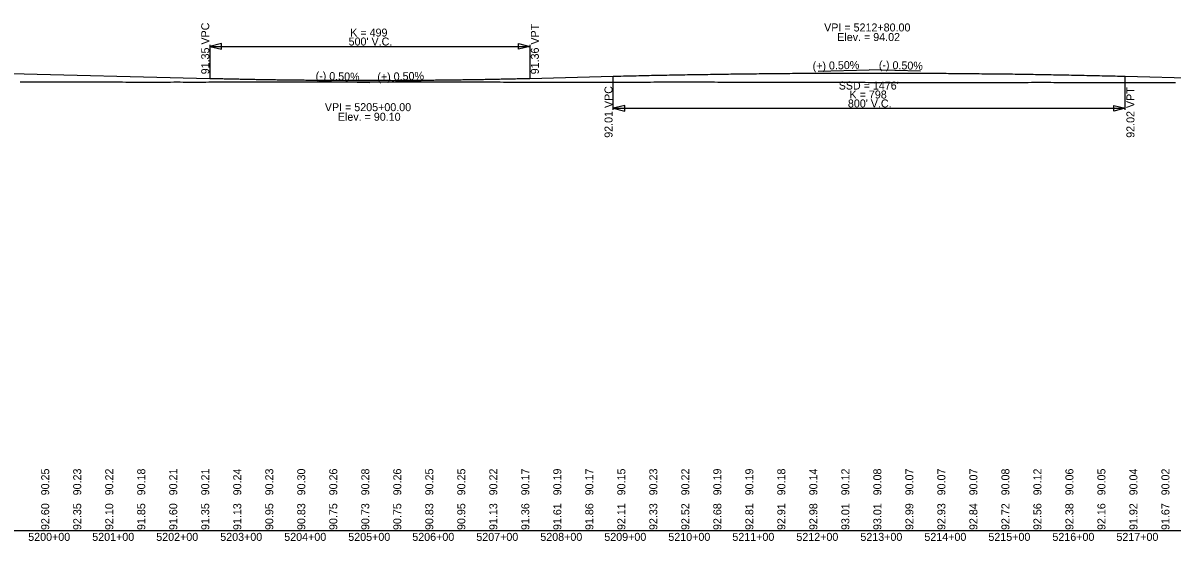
# Model space of a CAD drawing. Extents: x 2147288 to 2220488, y 740833 to 759333.
# Drawn here: x 2152339 to 2154136, y 742067 to 742877 of the extents above; entities that cross this region are included whole.
import ezdxf

# ---------------------------------------------------------------- set-up
doc = ezdxf.new("R2010")
doc.units = 0
for name, color, linetype in [('RD_DDB_GradeTX', 7, 'Continuous'), ('RD_DDB_Profile_EX', 7, 'Continuous'), ('RD_DDB_Profile_Lbl', 7, 'Continuous'), ('RD_DDB_Profile_PR', 7, 'Continuous'), ('RD_DDB_StaTX', 7, 'Continuous'), ('RD_DDB_StripGrade', 7, 'Continuous'), ('RD_DDB_VCLbl', 7, 'Continuous'), ('RD_GPK_Profile_Cell', 7, 'Continuous')]:
    doc.layers.add(name, color=color, linetype=linetype)

msp = doc.modelspace()

# ---------------------------------------------------------------- linework, layer by layer
at = {"layer": 'RD_DDB_GradeTX'}
for p, q in [((2153581.1, 742801.5), (2153661.1, 742803.5)), ((2153741.1, 742801.5), (2153661.1, 742803.5)), ((2152801.1, 742785.9), (2152881.1, 742783.9)), ((2152961.1, 742785.9), (2152881.1, 742783.9))]:
    msp.add_line(p, q, dxfattribs=at)
at = {"layer": 'RD_DDB_Profile_EX'}
for points in [[(2152334.6, 742784.9), (2152339.6, 742784.9), (2152344.6, 742784.8), (2152349.6, 742784.8), (2152354.6, 742784.8), (2152359.6, 742784.8), (2152364.6, 742784.7), (2152369.6, 742784.7), (2152374.6, 742784.7), (2152379.6, 742784.7), (2152384.6, 742784.7), (2152389.6, 742784.6), (2152394.6, 742784.6), (2152399.6, 742784.6), (2152404.6, 742784.6), (2152409.6, 742784.6), (2152414.6, 742784.6), (2152419.6, 742784.6), (2152424.6, 742784.6), (2152429.6, 742784.6), (2152434.6, 742784.6), (2152439.6, 742784.6), (2152444.6, 742784.6), (2152449.6, 742784.6), (2152454.6, 742784.6), (2152459.6, 742784.6), (2152464.6, 742784.6), (2152469.6, 742784.6), (2152474.6, 742784.5), (2152479.6, 742784.5), (2152484.6, 742784.5), (2152489.6, 742784.5), (2152494.6, 742784.5), (2152499.6, 742784.4), (2152504.6, 742784.4), (2152509.6, 742784.4), (2152514.6, 742784.4), (2152519.6, 742784.4), (2152524.6, 742784.4), (2152529.6, 742784.3), (2152534.6, 742784.3)], [(2152534.6, 742784.3), (2152539.6, 742784.3), (2152544.6, 742784.3), (2152549.6, 742784.3), (2152554.6, 742784.4), (2152559.6, 742784.4), (2152564.6, 742784.4), (2152569.6, 742784.4), (2152574.6, 742784.5), (2152579.6, 742784.5), (2152584.6, 742784.5), (2152589.6, 742784.4), (2152594.6, 742784.4), (2152599.6, 742784.4), (2152604.6, 742784.4), (2152609.6, 742784.4), (2152614.6, 742784.4), (2152619.6, 742784.4), (2152624.6, 742784.4), (2152629.6, 742784.5), (2152634.6, 742784.5), (2152639.6, 742784.5), (2152644.6, 742784.5), (2152649.6, 742784.6), (2152654.6, 742784.6), (2152659.6, 742784.6), (2152664.6, 742784.6), (2152669.6, 742784.6), (2152674.6, 742784.6), (2152679.6, 742784.6), (2152684.6, 742784.6), (2152689.6, 742784.7), (2152694.6, 742784.7), (2152699.6, 742784.7), (2152704.6, 742784.6), (2152709.6, 742784.6), (2152714.6, 742784.6), (2152719.6, 742784.6), (2152724.6, 742784.6), (2152729.6, 742784.6), (2152734.6, 742784.6), (2152739.6, 742784.6), (2152744.6, 742784.6), (2152749.6, 742784.6), (2152754.6, 742784.7), (2152759.6, 742784.7), (2152764.6, 742784.8), (2152769.6, 742784.8), (2152774.6, 742784.9), (2152779.6, 742784.9), (2152784.6, 742784.9), (2152789.6, 742784.9), (2152794.6, 742784.8), (2152799.6, 742784.8), (2152804.6, 742784.8), (2152809.6, 742784.8), (2152814.6, 742784.8), (2152819.6, 742784.8), (2152824.6, 742784.8), (2152829.6, 742784.7), (2152834.6, 742784.7), (2152839.6, 742784.7), (2152844.6, 742784.7), (2152849.6, 742784.7), (2152854.6, 742784.7), (2152859.6, 742784.7), (2152864.6, 742784.8), (2152869.6, 742784.8), (2152874.6, 742784.8), (2152879.6, 742784.8), (2152884.6, 742784.8), (2152889.6, 742784.9), (2152894.6, 742784.9), (2152899.6, 742784.8), (2152904.6, 742784.8), (2152909.6, 742784.8), (2152914.6, 742784.8), (2152919.6, 742784.8), (2152924.6, 742784.8), (2152929.6, 742784.7), (2152934.6, 742784.7), (2152939.6, 742784.7), (2152944.6, 742784.7), (2152949.6, 742784.7), (2152954.6, 742784.7), (2152959.6, 742784.7), (2152964.6, 742784.7), (2152969.6, 742784.7), (2152974.6, 742784.7), (2152979.6, 742784.7), (2152984.6, 742784.7), (2152989.6, 742784.7), (2152994.6, 742784.7), (2152999.6, 742784.7), (2153004.6, 742784.8), (2153009.6, 742784.8), (2153014.6, 742784.8), (2153019.6, 742784.7), (2153024.6, 742784.7), (2153029.6, 742784.7), (2153034.6, 742784.7)], [(2153034.6, 742784.7), (2153039.6, 742784.7), (2153044.6, 742784.8), (2153049.6, 742784.8), (2153054.6, 742784.9), (2153059.6, 742784.9), (2153064.6, 742784.8), (2153069.6, 742784.7), (2153074.6, 742784.6), (2153079.6, 742784.6), (2153084.6, 742784.5), (2153089.6, 742784.4), (2153094.6, 742784.4), (2153099.6, 742784.3), (2153104.6, 742784.3), (2153109.6, 742784.3), (2153114.6, 742784.3), (2153119.6, 742784.3), (2153124.6, 742784.3), (2153129.6, 742784.3), (2153134.6, 742784.3), (2153139.6, 742784.3), (2153144.6, 742784.3), (2153149.6, 742784.3), (2153154.6, 742784.3), (2153159.6, 742784.3), (2153164.6, 742784.3), (2153169.6, 742784.3), (2153174.6, 742784.4), (2153179.6, 742784.4), (2153184.6, 742784.4), (2153189.6, 742784.4), (2153194.6, 742784.3), (2153199.6, 742784.4), (2153204.6, 742784.4), (2153209.6, 742784.4), (2153214.6, 742784.4), (2153219.6, 742784.3), (2153224.6, 742784.3), (2153229.6, 742784.3), (2153234.6, 742784.3), (2153239.6, 742784.2), (2153244.6, 742784.2), (2153249.6, 742784.1), (2153254.6, 742784), (2153259.6, 742784.1), (2153264.6, 742784.1), (2153269.6, 742784.1), (2153274.6, 742784.1), (2153279.6, 742784.2), (2153284.6, 742784.2), (2153289.6, 742784.2), (2153294.6, 742784.3), (2153299.6, 742784.3), (2153304.6, 742784.4), (2153309.6, 742784.4), (2153314.6, 742784.3), (2153319.6, 742784.4), (2153324.6, 742784.5), (2153329.6, 742784.6), (2153334.6, 742784.6), (2153339.6, 742784.6), (2153344.6, 742784.6), (2153349.6, 742784.6), (2153354.6, 742784.6), (2153359.6, 742784.6), (2153364.6, 742784.6), (2153369.6, 742784.5), (2153374.6, 742784.5), (2153379.6, 742784.5), (2153384.6, 742784.6), (2153389.6, 742784.6), (2153394.6, 742784.6), (2153399.6, 742784.5), (2153404.6, 742784.5), (2153409.6, 742784.5), (2153414.6, 742784.5), (2153419.6, 742784.5), (2153424.6, 742784.4), (2153429.6, 742784.4), (2153434.6, 742784.3), (2153439.6, 742784.3), (2153444.6, 742784.3), (2153449.6, 742784.3), (2153454.6, 742784.3), (2153459.6, 742784.3), (2153464.6, 742784.3), (2153469.6, 742784.4), (2153474.6, 742784.4), (2153479.6, 742784.4), (2153484.6, 742784.4), (2153489.6, 742784.4), (2153494.6, 742784.4), (2153499.6, 742784.4), (2153504.6, 742784.4), (2153509.6, 742784.3), (2153514.6, 742784.3), (2153519.6, 742784.4), (2153524.6, 742784.4), (2153529.6, 742784.3), (2153534.6, 742784.3)], [(2153534.6, 742784.3), (2153539.6, 742784.3), (2153544.6, 742784.3), (2153549.6, 742784.3), (2153554.6, 742784.3), (2153559.6, 742784.2), (2153564.6, 742784.2), (2153569.6, 742784.2), (2153574.6, 742784.2), (2153579.6, 742784.2), (2153584.6, 742784.1), (2153589.6, 742784.1), (2153594.6, 742784.1), (2153599.6, 742784.1), (2153604.6, 742784), (2153609.6, 742784), (2153614.6, 742784), (2153619.6, 742784), (2153624.6, 742784), (2153629.6, 742784), (2153634.6, 742784), (2153639.6, 742784), (2153644.6, 742784), (2153649.6, 742784), (2153654.6, 742784), (2153659.6, 742783.9), (2153664.6, 742783.9), (2153669.6, 742783.9), (2153674.6, 742783.8), (2153679.6, 742783.8), (2153684.6, 742783.8), (2153689.6, 742783.8), (2153694.6, 742783.8), (2153699.6, 742783.8), (2153704.6, 742783.8), (2153709.6, 742783.8), (2153714.6, 742783.8), (2153719.6, 742783.8), (2153724.6, 742783.8), (2153729.6, 742783.8), (2153734.6, 742783.8), (2153739.6, 742783.8), (2153744.6, 742783.8), (2153749.6, 742783.8), (2153754.6, 742783.8), (2153759.6, 742783.8), (2153764.6, 742783.8), (2153769.6, 742783.8), (2153774.6, 742783.8), (2153779.6, 742783.8), (2153784.6, 742783.8), (2153789.6, 742783.8), (2153794.6, 742783.8), (2153799.6, 742783.8), (2153804.6, 742783.7), (2153809.6, 742783.7), (2153814.6, 742783.7), (2153819.6, 742783.7), (2153824.6, 742783.8), (2153829.6, 742783.8), (2153834.6, 742783.8), (2153839.6, 742783.8), (2153844.6, 742783.8), (2153849.6, 742783.8), (2153854.6, 742783.8), (2153859.6, 742783.8), (2153864.6, 742783.8), (2153869.6, 742783.8), (2153874.6, 742783.8), (2153879.6, 742783.8), (2153884.6, 742783.8), (2153889.6, 742783.9), (2153894.6, 742783.9), (2153899.6, 742783.9), (2153904.6, 742783.9), (2153909.6, 742783.9), (2153914.6, 742784), (2153919.6, 742784), (2153924.6, 742784), (2153929.6, 742784), (2153934.6, 742784), (2153939.6, 742784), (2153944.6, 742784), (2153949.6, 742783.9), (2153954.6, 742783.9), (2153959.6, 742783.8), (2153964.6, 742783.8), (2153969.6, 742783.8), (2153974.6, 742783.8), (2153979.6, 742783.7), (2153984.6, 742783.7), (2153989.6, 742783.7), (2153994.6, 742783.7), (2153999.6, 742783.7), (2154004.6, 742783.7), (2154009.6, 742783.7), (2154014.6, 742783.7), (2154019.6, 742783.7), (2154024.6, 742783.7), (2154029.6, 742783.7), (2154034.6, 742783.7)], [(2154034.6, 742783.7), (2154039.6, 742783.7), (2154044.6, 742783.7), (2154049.6, 742783.7), (2154054.6, 742783.7), (2154059.6, 742783.7), (2154064.6, 742783.7), (2154069.6, 742783.6), (2154074.6, 742783.6), (2154079.6, 742783.6), (2154084.6, 742783.6), (2154089.6, 742783.6), (2154094.6, 742783.6), (2154099.6, 742783.6), (2154104.6, 742783.6), (2154109.6, 742783.6), (2154114.6, 742783.5), (2154119.6, 742783.5), (2154124.6, 742783.6), (2154129.6, 742783.5), (2154134.6, 742783.5), (2154139.6, 742783.5)]]:
    msp.add_lwpolyline(points, dxfattribs=at)
at = {"layer": 'RD_DDB_Profile_PR'}
for p, q in [((2152281.1, 742798.9), (2152631.1, 742790.2)), ((2153131.1, 742790.2), (2153261.1, 742793.5)), ((2154061.1, 742793.5), (2154231.1, 742789.3))]:
    msp.add_line(p, q, dxfattribs=at)
for points in [[(2152631.1, 742790.2), (2152641.1, 742789.9), (2152651.1, 742789.7), (2152661.1, 742789.5), (2152671.1, 742789.3), (2152681.1, 742789.1), (2152691.1, 742788.9), (2152701.1, 742788.7), (2152711.1, 742788.5), (2152721.1, 742788.3), (2152731.1, 742788.2), (2152741.1, 742788), (2152751.1, 742787.9), (2152761.1, 742787.8), (2152771.1, 742787.7), (2152781.1, 742787.6), (2152791.1, 742787.5), (2152801.1, 742787.4), (2152811.1, 742787.3), (2152821.1, 742787.2), (2152831.1, 742787.2), (2152841.1, 742787.1), (2152851.1, 742787.1), (2152861.1, 742787.1), (2152871.1, 742787.1), (2152881.1, 742787.1), (2152891.1, 742787.1), (2152901.1, 742787.1), (2152911.1, 742787.1), (2152921.1, 742787.1), (2152931.1, 742787.2), (2152941.1, 742787.2), (2152951.1, 742787.3), (2152961.1, 742787.4), (2152971.1, 742787.5), (2152981.1, 742787.6), (2152991.1, 742787.7), (2153001.1, 742787.8), (2153011.1, 742787.9), (2153021.1, 742788.1), (2153031.1, 742788.2), (2153041.1, 742788.4), (2153051.1, 742788.5), (2153061.1, 742788.7), (2153071.1, 742788.9), (2153081.1, 742789.1), (2153091.1, 742789.3), (2153101.1, 742789.5), (2153111.1, 742789.7), (2153121.1, 742790), (2153131.1, 742790.2)], [(2153261.1, 742793.5), (2153277.1, 742793.9), (2153293.1, 742794.2), (2153309.1, 742794.6), (2153325.1, 742795), (2153341.1, 742795.3), (2153357.1, 742795.6), (2153373.1, 742795.9), (2153389.1, 742796.2), (2153405.1, 742796.4), (2153421.1, 742796.7), (2153437.1, 742796.9), (2153453.1, 742797.1), (2153469.1, 742797.3), (2153485.1, 742797.5), (2153501.1, 742797.7), (2153517.1, 742797.9), (2153533.1, 742798), (2153549.1, 742798.1), (2153565.1, 742798.2), (2153581.1, 742798.3), (2153597.1, 742798.4), (2153613.1, 742798.4), (2153629.1, 742798.5), (2153645.1, 742798.5), (2153661.1, 742798.5), (2153677.1, 742798.5), (2153693.1, 742798.5), (2153709.1, 742798.4), (2153725.1, 742798.4), (2153741.1, 742798.3), (2153757.1, 742798.2), (2153773.1, 742798.1), (2153789.1, 742798), (2153805.1, 742797.9), (2153821.1, 742797.7), (2153837.1, 742797.5), (2153853.1, 742797.4), (2153869.1, 742797.2), (2153885.1, 742797), (2153901.1, 742796.7), (2153917.1, 742796.5), (2153933.1, 742796.2), (2153949.1, 742795.9), (2153965.1, 742795.6), (2153981.1, 742795.3), (2153997.1, 742795), (2154013.1, 742794.6), (2154029.1, 742794.3), (2154045.1, 742793.9), (2154061.1, 742793.5)]]:
    msp.add_spline(points, degree=3, dxfattribs=at)
at = {"layer": 'RD_DDB_VCLbl'}
for p, q in [((2152631.1, 742842.7), (2152631.1, 742790.2)), ((2152631.1, 742840.2), (2153131.1, 742840.2)), ((2153131.1, 742842.7), (2153131.1, 742790.2)), ((2153261.1, 742741), (2153261.1, 742793.5)), ((2154061.1, 742741), (2154061.1, 742793.5)), ((2153261.1, 742743.5), (2154061.1, 742743.5))]:
    msp.add_line(p, q, dxfattribs=at)
for points in [[(2152649.1, 742844.7), (2152631.1, 742840.2), (2152649.1, 742835.7)], [(2153113.1, 742844.7), (2153131.1, 742840.2), (2153113.1, 742835.7)], [(2153279.1, 742748), (2153261.1, 742743.5), (2153279.1, 742739)], [(2154043.1, 742748), (2154061.1, 742743.5), (2154043.1, 742739)]]:
    msp.add_lwpolyline(points, close=True, dxfattribs=at)
at = {"layer": 'RD_GPK_Profile_Cell'}
msp.add_line((2148888.3, 742083.4), (2165888.3, 742083.4), dxfattribs=at)

# ---------------------------------------------------------------- texts
at = {"layer": 'RD_DDB_GradeTX'}
for s, rotation, p in [('(-) 0.50%', 358.5679, (2153676, 742805.1)), ('(-) 0.50%', 358.5679, (2152796.1, 742788.1)), ('(+) 0.50%', 1.439, (2152892.8, 742786.2)), ('(+) 0.50%', 1.439, (2153572.8, 742803.3))]:
    msp.add_text(s, height=12.5, rotation=rotation, dxfattribs=at).set_placement(p)
at = {"layer": 'RD_DDB_Profile_Lbl'}
for s, p in [('VPI = 5212+80.00', (2153590.7, 742863.5)), ('Elev. = 94.02', (2153611.2, 742848.5)), ('VPI = 5205+00.00', (2152810.7, 742738.9)), ('Elev. = 90.10', (2152831, 742723.9))]:
    msp.add_text(s, height=12.5, dxfattribs=at).set_placement(p)
at = {"layer": 'RD_DDB_StaTX'}
for s, p in [('5200+00', (2152347.3, 742067.2)), ('5201+00', (2152447.3, 742067.2)), ('5202+00', (2152547.3, 742067.2)), ('5203+00', (2152647.3, 742067.2)), ('5204+00', (2152747.3, 742067.2)), ('5205+00', (2152847.3, 742067.2)), ('5206+00', (2152947.3, 742067.2)), ('5207+00', (2153047.3, 742067.2)), ('5208+00', (2153147.3, 742067.2)), ('5209+00', (2153247.3, 742067.2)), ('5210+00', (2153347.3, 742067.2)), ('5211+00', (2153447.3, 742067.2)), ('5212+00', (2153547.3, 742067.2)), ('5213+00', (2153647.3, 742067.2)), ('5214+00', (2153747.3, 742067.2)), ('5215+00', (2153847.3, 742067.2)), ('5216+00', (2153947.3, 742067.2)), ('5217+00', (2154047.3, 742067.2))]:
    msp.add_text(s, height=12.5, dxfattribs=at).set_placement(p)
at = {"layer": 'RD_DDB_StripGrade'}
for s, p in [('91.35 VPC', (2152630.1, 742796.5)), ('91.36 VPT', (2153145, 742796.5)), ('92.01 VPC', (2153260.1, 742697.3)), ('92.02 VPT', (2154075.4, 742697.3)), ('90.25', (2152380.1, 742138.4)), ('90.23', (2152430.1, 742138.4)), ('90.22', (2152480.1, 742138.4)), ('90.18', (2152530.1, 742138.4)), ('90.21', (2152580.1, 742138.4)), ('90.21', (2152630.1, 742138.4)), ('90.24', (2152680.1, 742138.4)), ('90.23', (2152730.1, 742138.4)), ('90.30', (2152780.1, 742138.4)), ('90.26', (2152830.1, 742138.4)), ('90.28', (2152880.1, 742138.4)), ('90.26', (2152930.1, 742138.4)), ('90.25', (2152980.1, 742138.4)), ('90.25', (2153030.1, 742138.4)), ('90.22', (2153080.1, 742138.4)), ('90.17', (2153130.1, 742138.4)), ('90.19', (2153180.1, 742138.4)), ('90.17', (2153230.1, 742138.4)), ('90.15', (2153280.1, 742138.4)), ('90.23', (2153330.1, 742138.4)), ('90.22', (2153380.1, 742138.4)), ('90.19', (2153430.1, 742138.4)), ('90.19', (2153480.1, 742138.4)), ('90.18', (2153530.1, 742138.4)), ('90.14', (2153580.1, 742138.4)), ('90.12', (2153630.1, 742138.4)), ('90.08', (2153680.1, 742138.4)), ('90.07', (2153730.1, 742138.4)), ('90.07', (2153780.1, 742138.4)), ('90.07', (2153830.1, 742138.4)), ('90.08', (2153880.1, 742138.4)), ('90.12', (2153930.1, 742138.4)), ('90.06', (2153980.1, 742138.4)), ('90.05', (2154030.1, 742138.4)), ('90.04', (2154080.1, 742138.4)), ('90.02', (2154130.1, 742138.4)), ('92.60', (2152380.1, 742084.2)), ('92.35', (2152430.1, 742084.2)), ('92.10', (2152480.1, 742084.2)), ('91.85', (2152530.1, 742084.2)), ('91.60', (2152580.1, 742084.2)), ('91.35', (2152630.1, 742084.2)), ('91.13', (2152680.1, 742084.2)), ('90.95', (2152730.1, 742084.2)), ('90.83', (2152780.1, 742084.2)), ('90.75', (2152830.1, 742084.2)), ('90.73', (2152880.1, 742084.2)), ('90.75', (2152930.1, 742084.2)), ('90.83', (2152980.1, 742084.2)), ('90.95', (2153030.1, 742084.2)), ('91.13', (2153080.1, 742084.2)), ('91.36', (2153130.1, 742084.2)), ('91.61', (2153180.1, 742084.2)), ('91.86', (2153230.1, 742084.2)), ('92.11', (2153280.1, 742084.2)), ('92.33', (2153330.1, 742084.2)), ('92.52', (2153380.1, 742084.2)), ('92.68', (2153430.1, 742084.2)), ('92.81', (2153480.1, 742084.2)), ('92.91', (2153530.1, 742084.2)), ('92.98', (2153580.1, 742084.2)), ('93.01', (2153630.1, 742084.2)), ('93.01', (2153680.1, 742084.2)), ('92.99', (2153730.1, 742084.2)), ('92.93', (2153780.1, 742084.2)), ('92.84', (2153830.1, 742084.2)), ('92.72', (2153880.1, 742084.2)), ('92.56', (2153930.1, 742084.2)), ('92.38', (2153980.1, 742084.2)), ('92.16', (2154030.1, 742084.2)), ('91.92', (2154080.1, 742084.2)), ('91.67', (2154130.1, 742084.2))]:
    msp.add_text(s, height=12.5, rotation=90, dxfattribs=at).set_placement(p)
at = {"layer": 'RD_DDB_VCLbl'}
for s, p in [("500' V.C.", (2152847.8, 742841.5)), ('K = 499', (2152850.4, 742855.5)), ("SSD = 1476'", (2153613.4, 742772.7)), ('K = 798', (2153630.4, 742758.7)), ("800' V.C.", (2153627.8, 742744.7))]:
    msp.add_text(s, height=12.5, dxfattribs=at).set_placement(p)

doc.saveas('drawing.dxf')
